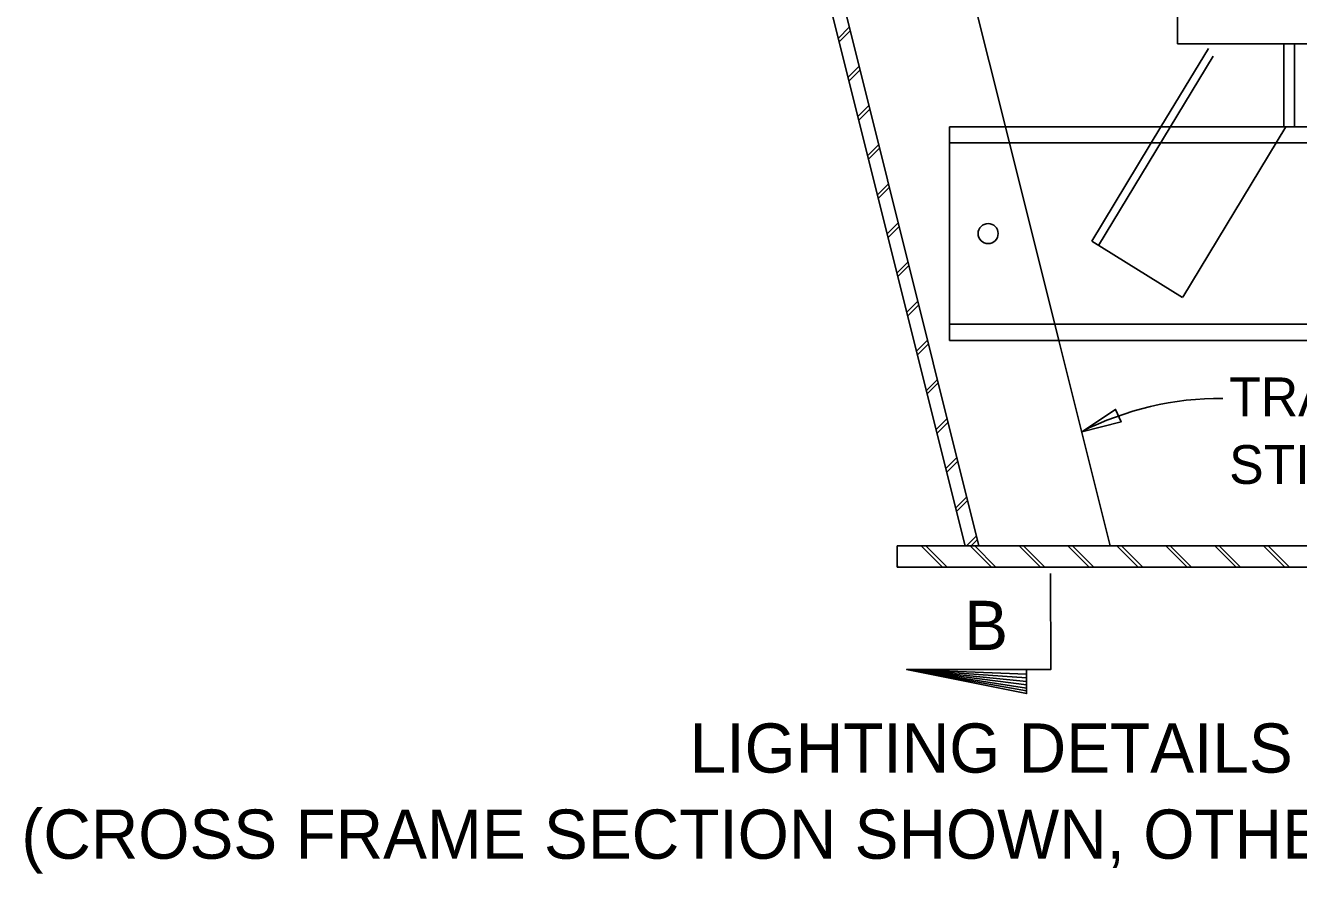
# Model space of a CAD drawing. Extents: x -1660015.2 to -1659984.9, y 2580594.2 to 2580616.7.
# Drawn here: x -1660014.974 to -1660010.005, y 2580595.519 to 2580598.829 of the extents above; entities that cross this region are included whole.
import ezdxf

# ---------------------------------------------------------------- set-up
doc = ezdxf.new("R2010")
doc.units = 0
for name, color, linetype in [('Default', 7, 'Continuous'), ('Miscellaneous', 7, 'Continuous'), ('PlotBorder_dp', 7, 'Continuous'), ('SheetLines_dp', 7, 'Continuous'), ('SteelGirder', 7, 'Continuous')]:
    doc.layers.add(name, color=color, linetype=linetype)

msp = doc.modelspace()

# ---------------------------------------------------------------- linework, layer by layer
at = {"layer": 'Default'}
for p, q in [((-1660010.0631, 2580598.7577), (-1660010.0631, 2580598.4333)), ((-1660010.0215, 2580598.7577), (-1660010.0215, 2580598.4333)), ((-1660010.7858, 2580597.9702), (-1660010.3387, 2580598.7094)), ((-1660011.1492, 2580598.4333), (-1660010.9408, 2580597.6)), ((-1660010.8123, 2580597.9867), (-1660010.5421, 2580598.4333)), ((-1660010.457, 2580597.7688), (-1660010.055, 2580598.4333)), ((-1660010.8123, 2580597.9867), (-1660010.4583, 2580597.7666))]:
    msp.add_line(p, q, dxfattribs=at)
at = {"layer": 'Miscellaneous'}
for p, q in [((-1660011.8015, 2580598.7794), (-1660011.7586, 2580598.8223)), ((-1660011.798, 2580598.7652), (-1660011.755, 2580598.8082)), ((-1660011.7633, 2580598.6266), (-1660011.7204, 2580598.6696)), ((-1660011.7598, 2580598.6125), (-1660011.7168, 2580598.6554)), ((-1660011.7252, 2580598.4739), (-1660011.6822, 2580598.5168)), ((-1660011.7216, 2580598.4597), (-1660011.6787, 2580598.5027)), ((-1660011.687, 2580598.3211), (-1660011.644, 2580598.3641)), ((-1660011.6834, 2580598.307), (-1660011.6405, 2580598.35)), ((-1660011.6488, 2580598.1684), (-1660011.6058, 2580598.2114)), ((-1660011.6453, 2580598.1543), (-1660011.6023, 2580598.1972)), ((-1660011.6106, 2580598.0157), (-1660011.5676, 2580598.0586)), ((-1660011.6071, 2580598.0015), (-1660011.5641, 2580598.0445)), ((-1660011.5724, 2580597.8629), (-1660011.5295, 2580597.9059)), ((-1660011.5689, 2580597.8488), (-1660011.5259, 2580597.8918)), ((-1660011.5342, 2580597.7102), (-1660011.4913, 2580597.7532)), ((-1660011.5307, 2580597.6961), (-1660011.4877, 2580597.739)), ((-1660011.4961, 2580597.5575), (-1660011.4531, 2580597.6004)), ((-1660011.4925, 2580597.5433), (-1660011.4496, 2580597.5863)), ((-1660011.4579, 2580597.4047), (-1660011.4149, 2580597.4477)), ((-1660011.4543, 2580597.3906), (-1660011.4114, 2580597.4336)), ((-1660011.4197, 2580597.252), (-1660011.3767, 2580597.295)), ((-1660011.4162, 2580597.2379), (-1660011.3732, 2580597.2808)), ((-1660011.3815, 2580597.0993), (-1660011.3385, 2580597.1422)), ((-1660011.378, 2580597.0851), (-1660011.335, 2580597.1281)), ((-1660011.3433, 2580596.9465), (-1660011.3004, 2580596.9895)), ((-1660011.3398, 2580596.9324), (-1660011.2968, 2580596.9754)), ((-1660011.301, 2580596.798), (-1660011.2622, 2580596.8368)), ((-1660011.3947, 2580596.7147), (-1660011.4779, 2580596.798)), ((-1660011.377, 2580596.7147), (-1660011.4603, 2580596.798)), ((-1660011.2037, 2580596.7147), (-1660011.287, 2580596.798)), ((-1660011.2833, 2580596.798), (-1660011.2586, 2580596.8226)), ((-1660011.1861, 2580596.7147), (-1660011.2693, 2580596.798)), ((-1660011.0128, 2580596.7147), (-1660011.0961, 2580596.798)), ((-1660010.9951, 2580596.7147), (-1660011.0784, 2580596.798)), ((-1660010.8219, 2580596.7147), (-1660010.9052, 2580596.798)), ((-1660010.8042, 2580596.7147), (-1660010.8875, 2580596.798)), ((-1660010.631, 2580596.7147), (-1660010.7143, 2580596.798)), ((-1660010.6133, 2580596.7147), (-1660010.6966, 2580596.798)), ((-1660010.4401, 2580596.7147), (-1660010.5233, 2580596.798)), ((-1660010.4224, 2580596.7147), (-1660010.5057, 2580596.798)), ((-1660010.2491, 2580596.7147), (-1660010.3324, 2580596.798)), ((-1660010.2315, 2580596.7147), (-1660010.3147, 2580596.798)), ((-1660010.0582, 2580596.7147), (-1660010.1415, 2580596.798)), ((-1660010.0405, 2580596.7147), (-1660010.1238, 2580596.798)), ((-1660011.5679, 2580596.7147), (-1660011.5725, 2580596.7193))]:
    msp.add_line(p, q, dxfattribs=at)
at = {"layer": 'SheetLines_dp'}
for p, q in [((-1660011.0665, 2580596.2976), (-1660011.5353, 2580596.3151)), ((-1660011.5353, 2580596.3151), (-1660011.0665, 2580596.2826)), ((-1660011.0665, 2580596.2688), (-1660011.5353, 2580596.3151)), ((-1660011.5353, 2580596.3151), (-1660011.0665, 2580596.2551)), ((-1660011.0665, 2580596.2426), (-1660011.5353, 2580596.3151)), ((-1660011.5353, 2580596.3151), (-1660011.0665, 2580596.2326))]:
    msp.add_line(p, q, dxfattribs=at)
msp.add_lwpolyline([(-1660010.8517, 2580597.2435), (-1660010.698, 2580597.2819), (-1660010.7193, 2580597.3304)], close=True, dxfattribs=at)
msp.add_lwpolyline([(-1660010.9728, 2580596.6901), (-1660010.9727, 2580596.3151), (-1660011.5353, 2580596.3151), (-1660011.0665, 2580596.2213), (-1660011.0665, 2580596.3151)], dxfattribs=at)
msp.add_ellipse((-1660010.3092, 2580596.0607), major_axis=(-0.0084, -1.3128), ratio=0.953713, start_param=3.141601, end_param=3.59647, dxfattribs=at)
at = {"layer": 'SteelGirder'}
for p, q in [((-1660012.8687, 2580603.0479), (-1660011.3062, 2580596.798)), ((-1660012.815, 2580603.0479), (-1660011.2525, 2580596.798)), ((-1660012.136, 2580602.3812), (-1660011.1489, 2580598.4333)), ((-1660010.5421, 2580598.4333), (-1660010.3572, 2580598.739)), ((-1660011.3671, 2580597.6), (-1660011.3671, 2580598.4333)), ((-1660011.3671, 2580598.4332), (-1660006.558, 2580598.4332)), ((-1660011.3671, 2580598.3708), (-1660006.558, 2580598.3708)), ((-1660011.3671, 2580597.6625), (-1660006.558, 2580597.6625)), ((-1660011.3671, 2580597.6), (-1660006.558, 2580597.6)), ((-1660010.9408, 2580597.6), (-1660010.7403, 2580596.798)), ((-1660010.8418, 2580596.798), (-1660011.5725, 2580596.798)), ((-1660011.5725, 2580596.798), (-1660011.5725, 2580596.7147)), ((-1660011.5725, 2580596.798), (-1660011.5725, 2580596.7147)), ((-1660007.3416, 2580596.798), (-1660010.8417, 2580596.798)), ((-1660006.558, 2580596.7147), (-1660011.5725, 2580596.7147))]:
    msp.add_line(p, q, dxfattribs=at)
msp.add_lwpolyline([(-1660010.4775, 2580600.8659), (-1660010.4775, 2580598.7577), (-1660009.6191, 2580598.7577)], dxfattribs=at)
msp.add_circle((-1660011.2168, 2580598.0166), 0.0391, dxfattribs=at)

# ---------------------------------------------------------------- texts
at = {"layer": 'PlotBorder_dp'}
msp.add_text('B', height=0.192, dxfattribs=at).set_placement((-1660011.3102, 2580596.3914))
at = {"layer": 'SheetLines_dp'}
for s, height, p in [('TRANSVERSE', 0.1512, (-1660010.2761, 2580597.3039)), ('STIFFENER', 0.1512, (-1660010.2761, 2580597.0398)), ('LIGHTING DETAILS FOR STEEL BOX GIRDER BRIDGE', 0.192, (-1660012.3816, 2580595.9128)), ('(CROSS FRAME SECTION SHOWN, OTHER TRANSVERSE STIFFENER SECTIONS SIMILAR)', 0.192, (-1660014.9904, 2580595.5768))]:
    msp.add_text(s, height=height, dxfattribs=at).set_placement(p)

doc.saveas('drawing.dxf')
